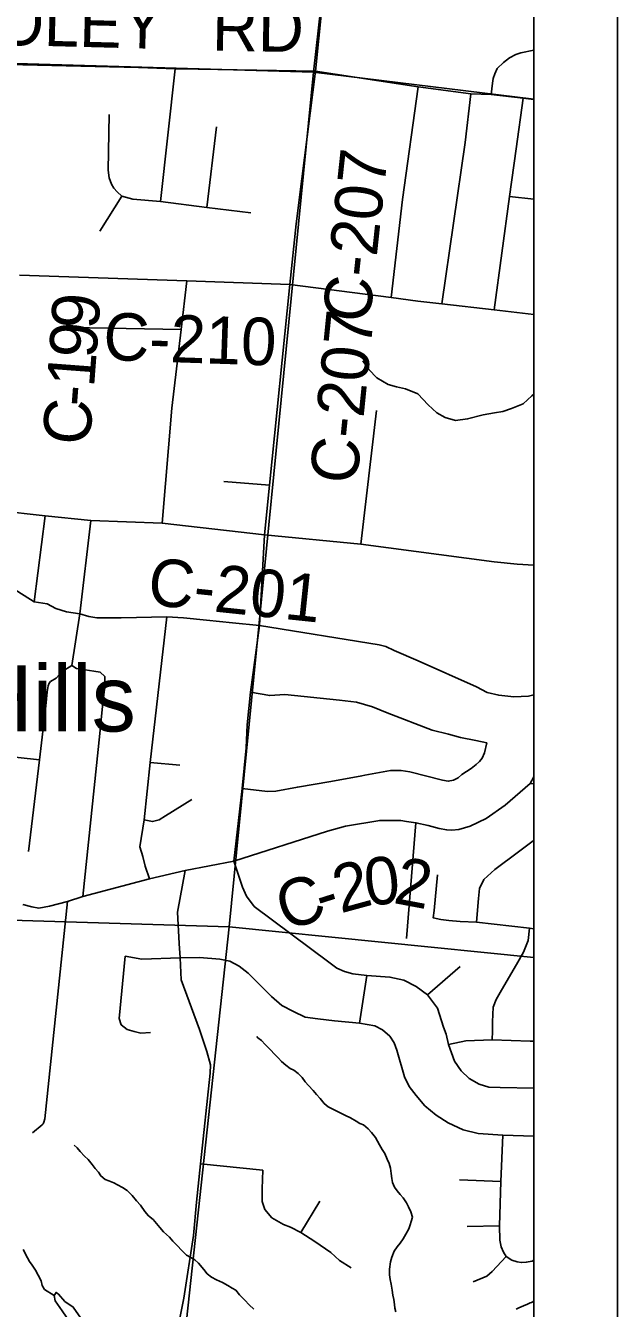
# Model space of a CAD drawing. Extents: x 0 to 43.4, y -8.1 to 22.
# Drawn here: x 8.292 to 9, y 14.72 to 16.255 of the extents above; entities that cross this region are included whole.
import ezdxf

# ---------------------------------------------------------------- set-up
doc = ezdxf.new("R2010")
doc.units = 0
for name, color, linetype in [('GM_X_City_Street', 7, 'Continuous'), ('GM_X_Corporation', 7, 'Continuous'), ('GM_X_County_Road', 7, 'Continuous'), ('GM_X_County_Road_Text', 7, 'Continuous'), ('GM_X_Minor_River', 7, 'Continuous'), ('GM_X_Township_Road', 7, 'Continuous'), ('GM_X_Unincorporated_Text', 7, 'Continuous'), ('SH_Data', 7, 'Continuous')]:
    doc.layers.add(name, color=color, linetype=linetype)

msp = doc.modelspace()

# ---------------------------------------------------------------- linework, layer by layer
at = {"layer": 'GM_X_City_Street'}
for p, q in [((8.7899, 15.9218), (8.8178, 16.1148)), ((8.8711, 16.0504), (8.9, 16.0473))]:
    msp.add_line(p, q, dxfattribs=at)
for points in [[(8.849, 16.1725), (8.8505, 16.1861), (8.8516, 16.1917), (8.8535, 16.1971), (8.8562, 16.2036), (8.8636, 16.2109), (8.8711, 16.2164), (8.8787, 16.2202), (8.8846, 16.2224), (8.9, 16.2254)], [(8.8526, 15.9146), (8.8711, 16.0504), (8.8789, 16.1075)], [(8.9, 15.9091), (8.8526, 15.9146), (8.7899, 15.9218), (8.7612, 15.9251)]]:
    msp.add_lwpolyline(points, dxfattribs=at)
at = {"layer": 'GM_X_Corporation'}
for points in [[(8.9, 14.3814), (8.9, 20.9), (2.1, 20.9)], [(8.9, 14.3814), (8.9, 17.1765)], [(7.4624, 14.2166), (7.5438, 15.2065), (8.5356, 15.1762), (8.4333, 14.2338)], [(8.9, 14.4255), (8.9, 15.1395), (8.5356, 15.1762), (8.4333, 14.2338)], [(8.9, 14.3814), (8.9, 14.7281), (8.8972, 14.7268), (8.8955, 14.7261), (8.8931, 14.725), (8.8924, 14.7247), (8.8878, 14.7226), (8.8821, 14.7201), (8.8788, 14.7186)]]:
    msp.add_lwpolyline(points, dxfattribs=at)
for points in [[(7.7575, 17.2431), (8.7485, 17.1931), (8.6363, 16.199), (7.6501, 16.228)], [(8.9, 16.1667), (8.9, 17.1752), (8.7485, 17.1931), (8.6363, 16.199)], [(8.6363, 16.199), (8.5356, 15.1762), (7.5438, 15.2065), (7.6501, 16.228)], [(8.9, 15.1395), (8.9, 16.1667), (8.6363, 16.199), (8.5356, 15.1762)]]:
    msp.add_lwpolyline(points, close=True, dxfattribs=at)
at = {"layer": 'GM_X_County_Road'}
for p, q in [((8.8955, 15.3479), (8.9, 15.3473)), ((8.541, 15.2549), (8.4827, 15.2437))]:
    msp.add_line(p, q, dxfattribs=at)
for points in [[(8.639, 16.2005), (8.6551, 16.3629), (8.6555, 16.3679), (8.663, 16.4343), (8.6708, 16.5382)], [(8.2716, 16.2083), (8.427, 16.2046), (8.4709, 16.2033), (8.4984, 16.2028), (8.639, 16.2005)], [(8.541, 15.2549), (8.5509, 15.3418), (8.5558, 15.3905), (8.5572, 15.4181), (8.561, 15.4573), (8.572, 15.537), (8.5777, 15.6455), (8.5837, 15.7048), (8.6082, 15.9452), (8.6156, 16.0177), (8.6224, 16.0714), (8.639, 16.2005)], [(8.639, 16.2005), (8.7615, 16.1815), (8.8247, 16.1733), (8.849, 16.1725), (8.8874, 16.1679), (8.9, 16.1664)], [(8.2845, 15.9562), (8.4847, 15.9494), (8.6082, 15.9452), (8.7294, 15.9293), (8.7612, 15.9251)], [(8.258, 15.6744), (8.3155, 15.6682), (8.37, 15.6624), (8.4552, 15.6595), (8.5777, 15.6455), (8.693, 15.6342), (8.8525, 15.6132), (8.88, 15.6102), (8.9, 15.6093)], [(8.2507, 15.5974), (8.302, 15.5653), (8.3176, 15.5627), (8.328, 15.5574), (8.3407, 15.5533), (8.3567, 15.5508), (8.3677, 15.5478), (8.3773, 15.5459), (8.4062, 15.5459), (8.461, 15.5472), (8.4808, 15.5459), (8.5083, 15.5434), (8.5394, 15.5402), (8.572, 15.537), (8.715, 15.5137), (8.7229, 15.5116), (8.733, 15.5068), (8.7618, 15.4946), (8.8314, 15.4636), (8.8441, 15.4568), (8.858, 15.4534), (8.8762, 15.4514), (8.8936, 15.4525), (8.9, 15.4538)], [(8.9, 15.3559), (8.8955, 15.3479), (8.8659, 15.322), (8.8431, 15.3059), (8.8238, 15.2966), (8.8105, 15.2929), (8.8021, 15.2919), (8.7958, 15.2923), (8.7868, 15.2939), (8.7735, 15.2976), (8.759, 15.3009), (8.7478, 15.3025), (8.7409, 15.3035), (8.7302, 15.3037), (8.7157, 15.3037), (8.6747, 15.2966), (8.6532, 15.2907), (8.541, 15.2549)], [(8.4827, 15.2437), (8.44, 15.2335), (8.3603, 15.2127), (8.342, 15.2065), (8.3205, 15.201), (8.3078, 15.1987), (8.2993, 15.2), (8.2887, 15.203)], [(8.4616, 14.6843), (8.4636, 14.6843), (8.4717, 14.6843), (8.4813, 14.7318), (8.4928, 14.807), (8.4965, 14.8467), (8.5013, 14.8926), (8.5127, 15.001), (8.513, 15.0112), (8.5089, 15.0272), (8.5001, 15.0533), (8.4779, 15.113), (8.4767, 15.1393), (8.4756, 15.1563), (8.4736, 15.1939), (8.4827, 15.2437)]]:
    msp.add_lwpolyline(points, dxfattribs=at)
at = {"layer": 'GM_X_Minor_River'}
for points in [[(8.6954, 15.8537), (8.7028, 15.8432), (8.7124, 15.8335), (8.7259, 15.8253), (8.7357, 15.8224), (8.7466, 15.8203), (8.7613, 15.8143), (8.7735, 15.8011), (8.7839, 15.7914), (8.794, 15.7858), (8.8064, 15.7821), (8.8209, 15.7841), (8.8396, 15.789), (8.8529, 15.7914), (8.8628, 15.7931), (8.8735, 15.7967), (8.8873, 15.8024), (8.8977, 15.8117), (8.9, 15.8137)], [(8.7349, 14.7156), (8.7339, 14.7199), (8.7332, 14.7244), (8.7326, 14.7302), (8.7313, 14.7352), (8.7307, 14.7413), (8.7293, 14.7485), (8.7283, 14.7543), (8.7273, 14.7596), (8.7275, 14.7665), (8.7285, 14.7752), (8.7302, 14.7809), (8.7331, 14.788), (8.7366, 14.7933), (8.7402, 14.7977), (8.7437, 14.803), (8.7469, 14.8086), (8.7505, 14.8146), (8.7522, 14.8195), (8.7534, 14.8236), (8.7547, 14.8286), (8.753, 14.8351), (8.7501, 14.8413), (8.7476, 14.8459), (8.7439, 14.8517), (8.7402, 14.856), (8.7365, 14.8603), (8.7332, 14.8646), (8.7311, 14.8703), (8.7301, 14.8749), (8.7295, 14.8811), (8.7285, 14.8872), (8.7268, 14.8929), (8.7246, 14.8983), (8.7218, 14.9049), (8.7185, 14.9099), (8.7156, 14.9153), (8.713, 14.9196), (8.7105, 14.9242), (8.7057, 14.9301), (8.702, 14.9344), (8.6961, 14.9391), (8.6919, 14.9407), (8.6875, 14.9435), (8.6807, 14.9475), (8.6747, 14.9504), (8.6683, 14.9536), (8.6597, 14.958), (8.6541, 14.9608), (8.6492, 14.9648), (8.6445, 14.9706), (8.64, 14.9757), (8.636, 14.9804), (8.6304, 14.9862), (8.6264, 14.9909), (8.6227, 14.996), (8.6179, 15.0007), (8.6127, 15.0046), (8.6085, 15.0067), (8.6033, 15.0106), (8.5981, 15.0149), (8.5944, 15.0192), (8.5892, 15.0243), (8.5852, 15.0286), (8.5785, 15.0353), (8.5741, 15.04), (8.57, 15.0435), (8.5688, 15.0448)], [(8.565, 14.7188), (8.5594, 14.724), (8.5543, 14.7294), (8.548, 14.7357), (8.5435, 14.7412), (8.539, 14.7436), (8.5338, 14.7468), (8.5274, 14.7504), (8.5203, 14.7536), (8.5143, 14.7568), (8.5091, 14.7611), (8.5051, 14.7662), (8.4988, 14.7736), (8.4943, 14.7776), (8.4898, 14.7803), (8.4846, 14.7832), (8.4787, 14.7887), (8.4731, 14.7949), (8.4683, 14.8), (8.4643, 14.8047), (8.4568, 14.8113), (8.4524, 14.8164), (8.4487, 14.8211), (8.4447, 14.8258), (8.4391, 14.8305), (8.4347, 14.8356), (8.4296, 14.8433), (8.4248, 14.8484), (8.4196, 14.8547), (8.4133, 14.8605), (8.4077, 14.8641), (8.4021, 14.8673), (8.3976, 14.8697), (8.3916, 14.8722), (8.387, 14.8738), (8.3818, 14.8782), (8.3793, 14.8828), (8.3752, 14.8871), (8.3716, 14.8918), (8.3668, 14.8976), (8.3623, 14.9016), (8.3571, 14.9074), (8.3535, 14.9117), (8.3499, 14.9151)], [(8.3262, 14.7351), (8.3146, 14.7422), (8.3117, 14.7468), (8.3104, 14.7526), (8.3071, 14.7595), (8.3039, 14.7653), (8.2998, 14.7712), (8.2965, 14.7758), (8.2944, 14.7801), (8.2889, 14.7901)], [(8.348, 14.6909), (8.3581, 14.708), (8.349, 14.7212), (8.3389, 14.7278), (8.3315, 14.7364), (8.3285, 14.7387), (8.3261, 14.735), (8.3275, 14.7285), (8.3356, 14.7165), (8.3407, 14.7092), (8.3462, 14.7011)]]:
    msp.add_lwpolyline(points, dxfattribs=at)
at = {"layer": 'GM_X_Township_Road'}
for p, q in [((8.4709, 16.2033), (8.4533, 16.0442)), ((8.8247, 16.1733), (8.8178, 16.1148)), ((8.8874, 16.1679), (8.8789, 16.1075)), ((8.5086, 16.0371), (8.5204, 16.1338)), ((8.407, 16.0506), (8.3806, 16.0088)), ((8.693, 15.6342), (8.7117, 15.7943)), ((8.5837, 15.7048), (8.529, 15.7093)), ((8.302, 15.5653), (8.3155, 15.6682)), ((8.37, 15.6624), (8.3567, 15.5508)), ((8.3085, 15.3762), (8.2301, 15.3849)), ((8.4411, 15.3729), (8.4765, 15.3697)), ((8.759, 15.3009), (8.7478, 15.1622)), ((8.7728, 15.0948), (8.812, 15.1287)), ((8.7001, 15.1181), (8.6915, 15.0609)), ((8.5013, 14.8926), (8.576, 14.8849)), ((8.811, 14.8736), (8.8606, 14.8716)), ((8.6211, 14.8105), (8.644, 14.8479)), ((8.8202, 14.8177), (8.859, 14.8185)), ((8.898, 14.7762), (8.9, 14.7772))]:
    msp.add_line(p, q, dxfattribs=at)
for points in [[(8.7615, 16.1815), (8.7429, 16.0466), (8.7294, 15.9293)], [(8.5616, 16.031), (8.5086, 16.0371), (8.4533, 16.0442), (8.4203, 16.047), (8.407, 16.0506), (8.4015, 16.0561), (8.3975, 16.0605), (8.3947, 16.0652), (8.3919, 16.0728), (8.3908, 16.0819), (8.392, 16.1484)], [(8.4552, 15.6595), (8.467, 15.7971), (8.4779, 15.8913), (8.4847, 15.9494)], [(8.4779, 15.8913), (8.3684, 15.8932), (8.3315, 15.8936)], [(8.3567, 15.5508), (8.3473, 15.4892), (8.3357, 15.482), (8.3284, 15.4738), (8.3219, 15.4698), (8.3202, 15.4677), (8.3188, 15.4646), (8.3178, 15.4574), (8.3162, 15.4408), (8.3085, 15.3762), (8.2953, 15.2665)], [(8.461, 15.5472), (8.4411, 15.3729), (8.4339, 15.3042), (8.4287, 15.2721), (8.4321, 15.2605), (8.4351, 15.2489), (8.44, 15.2335)], [(8.3473, 15.4892), (8.3528, 15.4856), (8.3734, 15.4823), (8.3812, 15.4809), (8.3867, 15.476), (8.3867, 15.4702), (8.3867, 15.4628), (8.3858, 15.4575), (8.3842, 15.4443), (8.3806, 15.4077), (8.3603, 15.2127)], [(8.561, 15.4573), (8.584, 15.4531), (8.6021, 15.4542), (8.6676, 15.4476), (8.688, 15.4451), (8.707, 15.4396), (8.7246, 15.4325), (8.7783, 15.4116), (8.7978, 15.4068), (8.8124, 15.4028), (8.8306, 15.3992), (8.8438, 15.3964)], [(8.8438, 15.3964), (8.8412, 15.3845), (8.8383, 15.378), (8.8352, 15.3743), (8.831, 15.3707), (8.8251, 15.3659), (8.8139, 15.3586), (8.8095, 15.3546), (8.8039, 15.3517), (8.7977, 15.3505), (8.7907, 15.3518), (8.7517, 15.3619), (8.7415, 15.3634), (8.7284, 15.3633), (8.698, 15.3578), (8.6942, 15.3571)], [(8.6942, 15.3571), (8.6571, 15.3503), (8.6172, 15.3436), (8.5915, 15.3388), (8.5813, 15.3384), (8.5509, 15.3418)], [(8.4339, 15.3042), (8.4438, 15.3023), (8.4519, 15.3042), (8.4593, 15.3089), (8.4907, 15.3285)], [(8.9, 15.2798), (8.8991, 15.2792), (8.8816, 15.2662), (8.8534, 15.2447), (8.8401, 15.2327), (8.8352, 15.2223), (8.8338, 15.21), (8.8315, 15.1818)], [(8.541, 15.2549), (8.5516, 15.2237), (8.5563, 15.213), (8.5654, 15.2006), (8.6546, 15.1338), (8.6644, 15.1267), (8.6734, 15.1226), (8.6834, 15.1201), (8.7001, 15.1181), (8.7279, 15.1161), (8.7446, 15.1124), (8.7593, 15.105), (8.7728, 15.0948), (8.7847, 15.0789), (8.7918, 15.0562), (8.7953, 15.0476), (8.7979, 15.0353), (8.8051, 15.0156), (8.8133, 15.0037), (8.8226, 14.9947), (8.8345, 14.9878), (8.8463, 14.9845), (8.8598, 14.9841), (8.9, 14.983)], [(8.7848, 15.2386), (8.7807, 15.1957), (8.7797, 15.1869), (8.7886, 15.1851), (8.7982, 15.1839), (8.8119, 15.1828), (8.8315, 15.1818), (8.8947, 15.1745), (8.9, 15.174)], [(8.342, 15.2065), (8.3151, 14.9463), (8.3139, 14.9425), (8.313, 14.9406), (8.3119, 14.9391), (8.3003, 14.9296)], [(8.8502, 15.0411), (8.8506, 15.0515), (8.8506, 15.0625), (8.8516, 15.0801), (8.8549, 15.0893), (8.8612, 15.1003), (8.8794, 15.1312), (8.8878, 15.1461), (8.8933, 15.1598), (8.8947, 15.1745)], [(8.4414, 15.0499), (8.4299, 15.0491), (8.4219, 15.051), (8.4134, 15.0532), (8.4062, 15.059), (8.4039, 15.0664), (8.4112, 15.141), (8.431, 15.1377), (8.4767, 15.1393)], [(8.4767, 15.1393), (8.5, 15.1394), (8.5243, 15.1377), (8.5364, 15.135), (8.5474, 15.1292), (8.5584, 15.1207), (8.5862, 15.0929), (8.5986, 15.0821), (8.6123, 15.075), (8.6264, 15.0681), (8.6415, 15.066), (8.6615, 15.0638), (8.6915, 15.0609)], [(8.6915, 15.0609), (8.7097, 15.0576), (8.7191, 15.0531), (8.7277, 15.0454), (8.7328, 15.0374), (8.736, 15.0286), (8.7452, 14.9966), (8.751, 14.9851), (8.7593, 14.9743), (8.7698, 14.9619), (8.7832, 14.9508), (8.7975, 14.9416), (8.8156, 14.9333), (8.8333, 14.9289), (8.8628, 14.927), (8.9, 14.9257)], [(8.7979, 15.0353), (8.8188, 15.0399), (8.8502, 15.0411), (8.8958, 15.0395), (8.9, 15.0393)], [(8.898, 14.7762), (8.8911, 14.7748), (8.8853, 14.7744), (8.88, 14.7754), (8.8739, 14.7774), (8.867, 14.7815), (8.8637, 14.787), (8.8609, 14.7932), (8.8592, 14.8011), (8.859, 14.8185), (8.8606, 14.8716), (8.8628, 14.927)], [(8.576, 14.8849), (8.5749, 14.8628), (8.5752, 14.8474), (8.5782, 14.8378), (8.5867, 14.8278), (8.6005, 14.8201), (8.609, 14.8166), (8.6211, 14.8105), (8.6379, 14.7995), (8.6572, 14.7863), (8.6676, 14.7769), (8.6814, 14.7681)], [(8.8273, 14.7513), (8.8437, 14.7582), (8.8504, 14.7638), (8.867, 14.7815)]]:
    msp.add_lwpolyline(points, dxfattribs=at)
at = {"layer": 'SH_Data'}
for p, q in [((9, 21), (9, 14)), ((8.9, 20.9), (8.9, 14.1))]:
    msp.add_line(p, q, dxfattribs=at)

# ---------------------------------------------------------------- texts
at = {"layer": 'GM_X_County_Road_Text'}
for s, height, rotation, p in [('FOLEY', 0.05682, 358.5154, (8.2079, 16.2333)), ('RD', 0.05682, 359.0128, (8.5147, 16.225)), ('C-207', 0.05682, 83.8103, (8.7034, 15.8978)), ('9', 0.0568, 86.1148, (8.3789, 15.8905)), ('C-210', 0.05682, 358.0725, (8.3843, 15.8548)), ('C-207', 0.05682, 84.2359, (8.6882, 15.7049)), ('9', 0.0568, 85.8234, (8.3764, 15.8556)), ('1', 0.0568, 85.7243, (8.3738, 15.8209)), ('-', 0.0568, 85.6925, (8.372, 15.7978)), ('C', 0.0568, 85.6901, (8.3686, 15.7516)), ('C-201', 0.05682, 353.984, (8.4365, 15.5621)), ('0', 0.0568, 6.2467, (8.7002, 15.201)), ('2', 0.0568, 15.2799, (8.6688, 15.1922)), ('2', 0.0568, 349.3195, (8.7306, 15.205)), ('C', 0.0568, 17.7157, (8.6027, 15.1711)), ('-', 0.0568, 17.6296, (8.6471, 15.1853))]:
    msp.add_text(s, height=height, rotation=rotation, dxfattribs=at).set_placement(p)
at = {"layer": 'GM_X_Unincorporated_Text'}
msp.add_text('Delhi Hills', height=0.078977, rotation=0, dxfattribs=at).set_placement((7.9543, 15.4101))

doc.saveas('drawing.dxf')
